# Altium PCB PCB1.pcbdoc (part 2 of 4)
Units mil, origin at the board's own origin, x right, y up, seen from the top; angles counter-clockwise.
Board outline 2559.1 x 3937 mil, 4 copper layers (Top Layer, Inner1, Inner2, Bottom Layer), stack 102.8 mil thick; 377 components, 358 nets, 1639 pads, 361 vias.
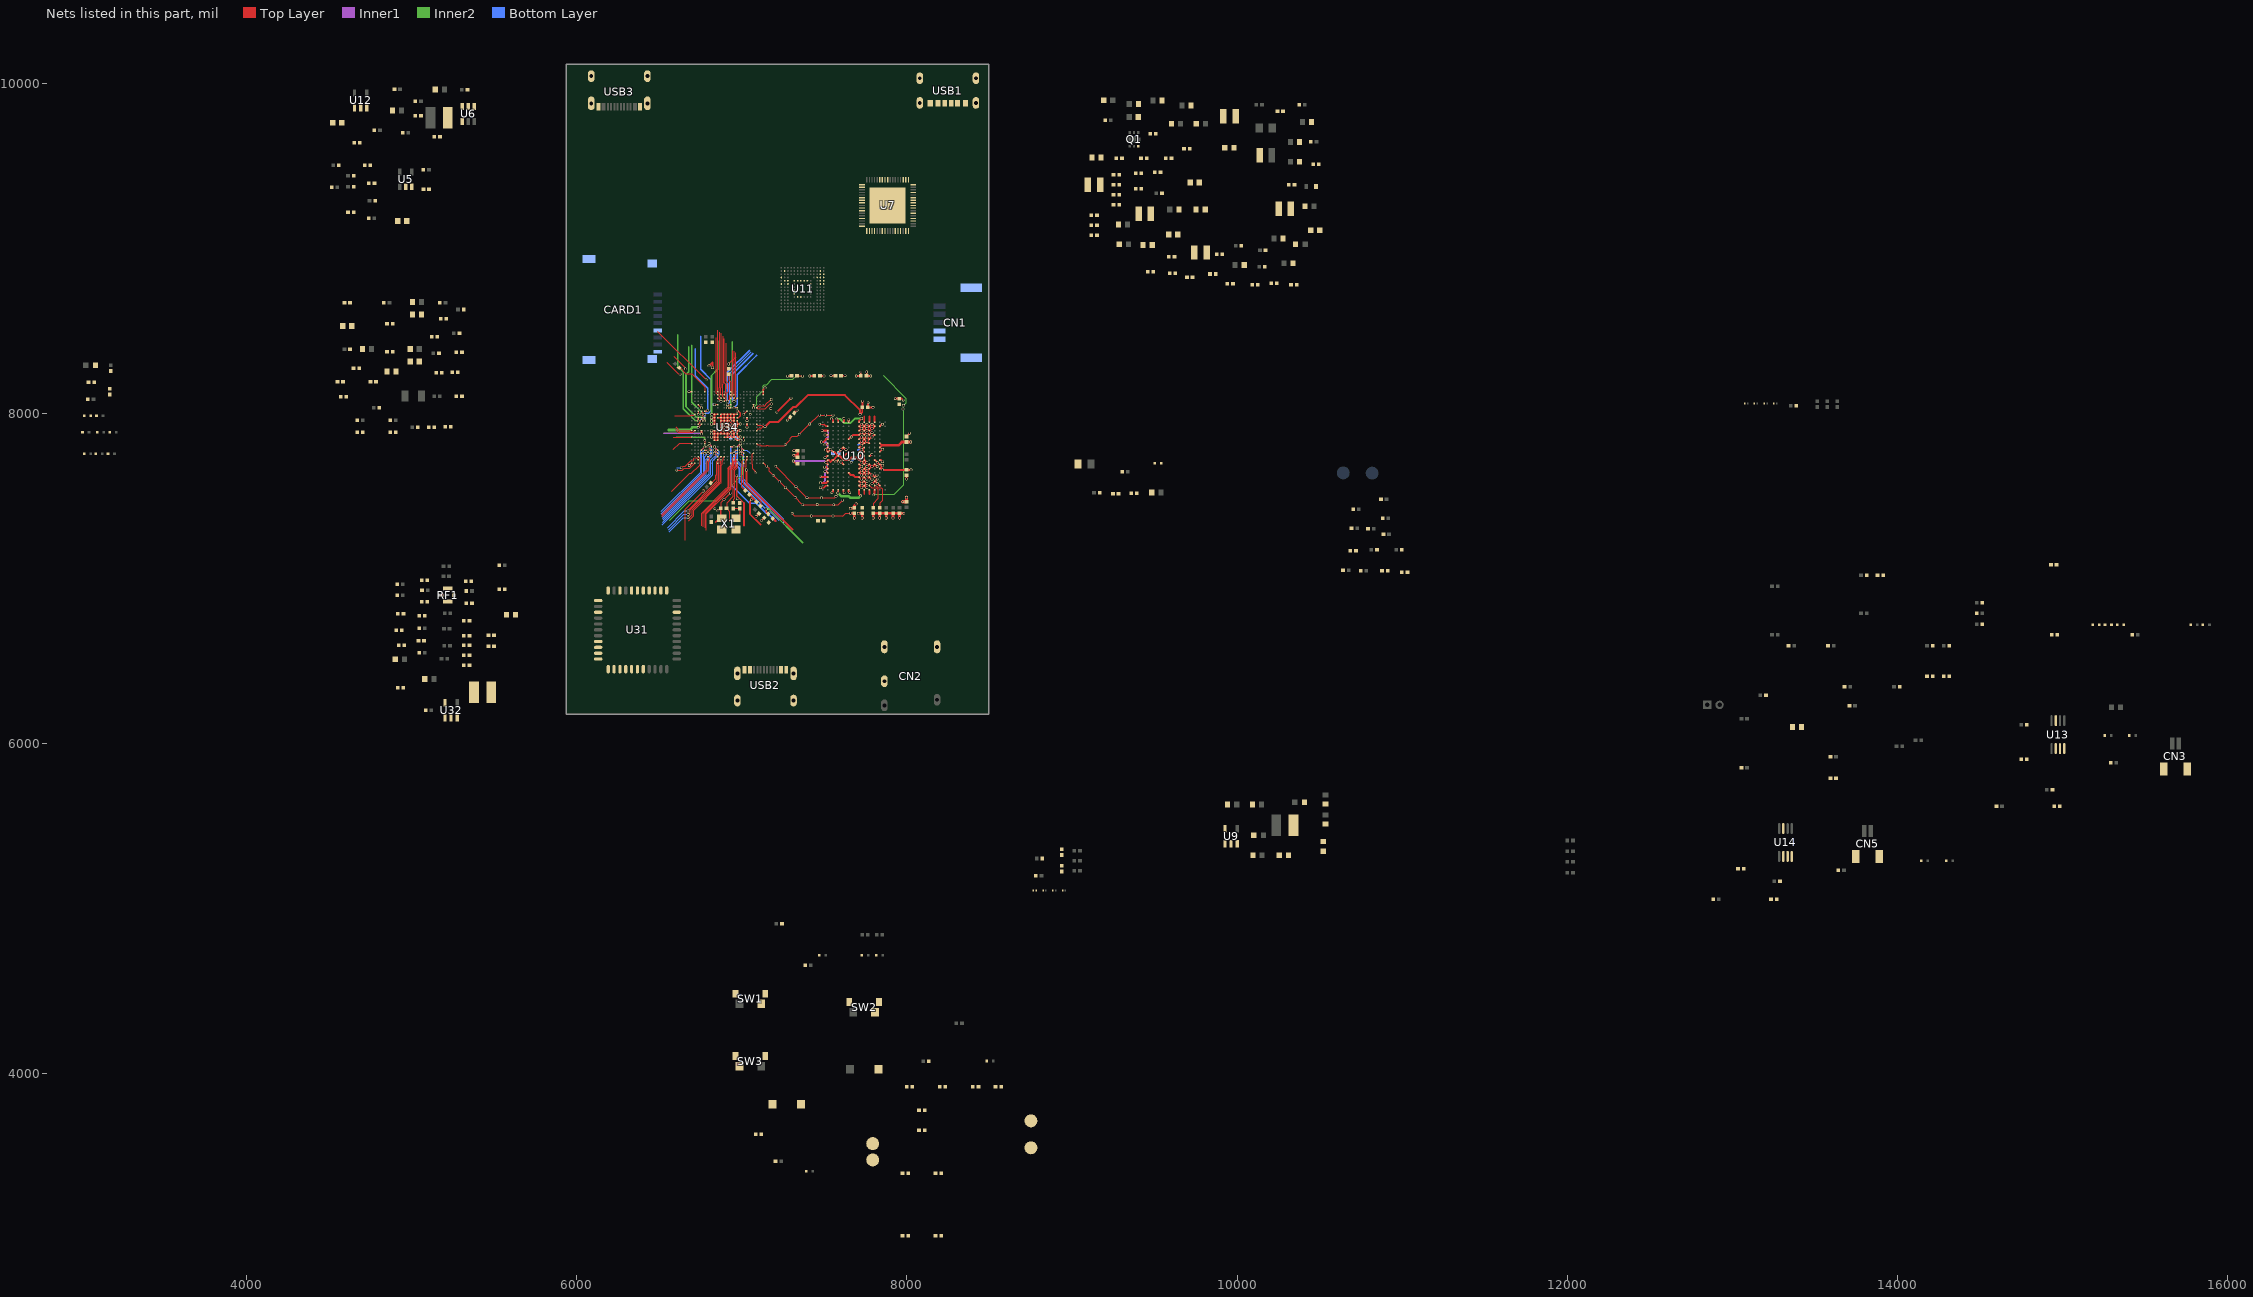
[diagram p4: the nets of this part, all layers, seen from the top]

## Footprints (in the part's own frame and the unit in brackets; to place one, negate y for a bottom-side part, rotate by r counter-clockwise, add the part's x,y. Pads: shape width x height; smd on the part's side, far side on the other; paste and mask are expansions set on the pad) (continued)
TF-SMD_TF-01A [mil]
  rect 23.6x51.2 smd paste+0 mask+2: 1(90.5,207.8) 2(47.2,207.8) 3(3.9,207.8) 4(-39.4,207.8) 5(-82.7,207.8) 6(-126,207.8) 7(-169.3,207.8) 8(-212.6,207.8) 9(-255.9,207.8)
  rect 47.2x55.1 smd paste+0 mask+2: 10(-299.2,174.3) 13(278.7,174.3)
  rect 47.2x78.7 smd paste+0 mask+2: 11(-305.5,-207.7) 12(305.5,-207.7)
  Board Outline Layer lines w0.1: -194.9,-235.3 -191.1,-234.9 -187.4,-233.8 -184,-232 -181,-229.6 -178.5,-226.6 -176.7,-223.2 -175.6,-219.5 -175.2,-215.6 -175.6,-211.8 -176.7,-208.1 -178.5,-204.7 -181,-201.7 -184,-199.3 -187.4,-197.4 -191.1,-196.3 -194.9,-195.9 -198.8,-196.3 -202.4,-197.4 -205.8,-199.3 -208.8,-201.7 -211.3,-204.7 -213.1,-208.1 -214.2,-211.8 -214.6,-215.6 -214.2,-219.5 -213.1,-223.2 -211.3,-226.6 -208.8,-229.6 -205.8,-232 -202.4,-233.8 -198.8,-234.9 -194.9,-235.3 ; 120.1,-235.2 123.9,-234.8 127.6,-233.7 131,-231.9 134,-229.5 136.4,-226.5 138.2,-223.1 139.4,-219.4 139.7,-215.5 139.4,-211.7 138.2,-208 136.4,-204.6 134,-201.6 131,-199.2 127.6,-197.3 123.9,-196.2 120.1,-195.8 116.2,-196.2 112.5,-197.3 109.1,-199.2 106.1,-201.6 103.7,-204.6 101.9,-208 100.7,-211.7 100.4,-215.5 100.7,-219.4 101.9,-223.1 103.7,-226.5 106.1,-229.5 109.1,-231.9 112.5,-233.7 116.2,-234.8 120.1,-235.2
  Board Outline Layer region: -175.2,-215.6 -175.6,-219.5 -176.7,-223.2 -178.5,-226.6 -181,-229.6 -184,-232 -187.4,-233.8 -191.1,-234.9 -194.9,-235.3 -198.8,-234.9 -202.4,-233.8 -205.8,-232 -208.8,-229.6 -211.3,-226.6 -213.1,-223.2 -214.2,-219.5 -214.6,-215.6 -214.2,-211.8 -213.1,-208.1 -211.3,-204.7 -208.8,-201.7 -205.8,-199.3 -202.4,-197.4 -198.8,-196.3 -194.9,-195.9 -191.1,-196.3 -187.4,-197.4 -184,-199.3 -181,-201.7 -178.5,-204.7 -176.7,-208.1 -175.6,-211.8
  Board Outline Layer region: -175.2,-215.6 -175.6,-219.5 -176.7,-223.2 -178.5,-226.6 -181,-229.6 -184,-232 -187.4,-233.8 -191.1,-234.9 -194.9,-235.3 -198.8,-234.9 -202.4,-233.8 -205.8,-232 -208.8,-229.6 -211.3,-226.6 -213.1,-223.2 -214.2,-219.5 -214.6,-215.6 -214.2,-211.8 -213.1,-208.1 -211.3,-204.7 -208.8,-201.7 -205.8,-199.3 -202.4,-197.4 -198.8,-196.3 -194.9,-195.9 -191.1,-196.3 -187.4,-197.4 -184,-199.3 -181,-201.7 -178.5,-204.7 -176.7,-208.1 -175.6,-211.8
  Board Outline Layer region: 139.7,-215.5 139.4,-219.4 138.2,-223.1 136.4,-226.5 134,-229.5 131,-231.9 127.6,-233.7 123.9,-234.8 120.1,-235.2 116.2,-234.8 112.5,-233.7 109.1,-231.9 106.1,-229.5 103.7,-226.5 101.9,-223.1 100.7,-219.4 100.4,-215.5 100.7,-211.7 101.9,-208 103.7,-204.6 106.1,-201.6 109.1,-199.2 112.5,-197.3 116.2,-196.2 120.1,-195.8 123.9,-196.2 127.6,-197.3 131,-199.2 134,-201.6 136.4,-204.6 138.2,-208 139.4,-211.7
  Board Outline Layer region: 139.7,-215.5 139.4,-219.4 138.2,-223.1 136.4,-226.5 134,-229.5 131,-231.9 127.6,-233.7 123.9,-234.8 120.1,-235.2 116.2,-234.8 112.5,-233.7 109.1,-231.9 106.1,-229.5 103.7,-226.5 101.9,-223.1 100.7,-219.4 100.4,-215.5 100.7,-211.7 101.9,-208 103.7,-204.6 106.1,-201.6 109.1,-199.2 112.5,-197.3 116.2,-196.2 120.1,-195.8 123.9,-196.2 127.6,-197.3 131,-199.2 134,-201.6 136.4,-204.6 138.2,-208 139.4,-211.7
  Multi-Layer board cut-out: -175.2,-215.6 -175.6,-219.5 -176.7,-223.2 -178.5,-226.6 -181,-229.6 -184,-232 -187.4,-233.8 -191.1,-234.9 -194.9,-235.3 -198.8,-234.9 -202.4,-233.8 -205.8,-232 -208.8,-229.6 -211.3,-226.6 -213.1,-223.2 -214.2,-219.5 -214.6,-215.6 -214.2,-211.8 -213.1,-208.1 -211.3,-204.7 -208.8,-201.7 -205.8,-199.3 -202.4,-197.4 -198.8,-196.3 -194.9,-195.9 -191.1,-196.3 -187.4,-197.4 -184,-199.3 -181,-201.7 -178.5,-204.7 -176.7,-208.1 -175.6,-211.8
  Multi-Layer board cut-out: 139.7,-215.5 139.4,-219.4 138.2,-223.1 136.4,-226.5 134,-229.5 131,-231.9 127.6,-233.7 123.9,-234.8 120.1,-235.2 116.2,-234.8 112.5,-233.7 109.1,-231.9 106.1,-229.5 103.7,-226.5 101.9,-223.1 100.7,-219.4 100.4,-215.5 100.7,-211.7 101.9,-208 103.7,-204.6 106.1,-201.6 109.1,-199.2 112.5,-197.3 116.2,-196.2 120.1,-195.8 123.9,-196.2 127.6,-197.3 131,-199.2 134,-201.6 136.4,-204.6 138.2,-208 139.4,-211.7
  silkscreen extent -290,-376 290,196
TSOT-23-5_L2.9-W1.6-P0.95-LS2.8-BL#1 [mil]
  rect 20.9x41.1 smd paste+0 mask+2: 1(-37.4,-45.2) 2(0,-45.2) 3(37.4,-45.2) 4(37.4,45.2) 5(-37.4,45.2)
  silkscreen extent -72,-57 61,36
TSOT-23-5_L2.9-W1.6-P0.95-LS2.8-BL#2 [mil]
  rect 20.9x41.1 smd paste+0 mask+2: 1(-37.4,-45.1) 2(0,-45.1) 3(37.4,-45.1) 4(37.4,45.2) 5(-37.4,45.2)
  silkscreen extent -72,-57 61,36
USB-C-SMD_TYPE-C-6P [mil]
  oval 39.4x70.9 hole 23.6 slot 55.1 at 90 deg paste+0 mask+2: 1(-170.1,-75.8) 1(-170.1,73.8) 2(170,-75.8) 2(170,73.8)
  rect 27.6x39.4 smd paste-3937 mask+2: A5(-19.7,75.8) B5(19.7,75.8)
  rect 29.5x39.4 smd paste-3937 mask+2: A9(59.1,75.8) B9(-59,75.8)
  rect 31.5x39.4 smd paste-3937 mask+2: A12(106.3,75.8) B12(-106.3,75.8)
  silkscreen extent -176,-178 176,99
USB-C-SMD_XUNPU_TYPEC-304A-ACP16L#1 [mil]
  oval 39.4x82.7 hole 23.6 slot 66.9 at 90 deg paste+0 mask+2: 25(170.1,71.1) 28(-170,71.1)
  oval 39.4x70.9 hole 23.6 slot 55.1 at 90 deg paste+0 mask+2: 26(170.1,-93.4) 27(-170,-93.4)
  rect 11.8x45.3 smd paste-3937 mask+2: A1(-131.9,93.4) A4(-100.4,93.4) A5(-49.2,93.4) A6(-9.8,93.4) A7(9.9,93.4) A8(49.2,93.4) A9(100.4,93.4) A12(131.9,93.4) B1(120.1,93.4) B4(88.6,93.4) B5(68.9,93.4) B6(29.6,93.4) B7(-29.5,93.4) B8(-68.9,93.4) B9(-88.5,93.4) B12(-120,93.4)
  Board Outline Layer lines w0.1: -126.5,51.5 -126.2,48.4 -125.1,45.5 -123.3,43 -121,40.9 -118.3,39.5 -115.3,38.8 -112.2,38.8 -109.2,39.5 -106.5,40.9 -104.2,43 -102.4,45.5 -101.3,48.4 -100.9,51.5 -101.3,54.5 -102.4,57.4 -104.2,60 -106.5,62 -109.2,63.4 -112.2,64.2 -115.3,64.2 -118.3,63.4 -121,62 -123.3,60 -125.1,57.4 -126.2,54.5 -126.5,51.5 ; 101,51.5 101.4,48.4 102.5,45.5 104.2,43 106.5,40.9 109.3,39.5 112.3,38.8 115.4,38.8 118.4,39.5 121.1,40.9 123.4,43 125.1,45.5 126.2,48.4 126.6,51.5 126.2,54.5 125.1,57.4 123.4,60 121.1,62 118.4,63.4 115.4,64.2 112.3,64.2 109.3,63.4 106.5,62 104.2,60 102.5,57.4 101.4,54.5 101,51.5
  Board Outline Layer region: -100.9,51.5 -101.3,48.4 -102.4,45.5 -104.2,43 -106.5,40.9 -109.2,39.5 -112.2,38.8 -115.3,38.8 -118.3,39.5 -121,40.9 -123.3,43 -125.1,45.5 -126.2,48.4 -126.5,51.5 -126.2,54.5 -125.1,57.4 -123.3,60 -121,62 -118.3,63.4 -115.3,64.2 -112.2,64.2 -109.2,63.4 -106.5,62 -104.2,60 -102.4,57.4 -101.3,54.5
  Board Outline Layer region: -100.9,51.5 -101.3,48.4 -102.4,45.5 -104.2,43 -106.5,40.9 -109.2,39.5 -112.2,38.8 -115.3,38.8 -118.3,39.5 -121,40.9 -123.3,43 -125.1,45.5 -126.2,48.4 -126.5,51.5 -126.2,54.5 -125.1,57.4 -123.3,60 -121,62 -118.3,63.4 -115.3,64.2 -112.2,64.2 -109.2,63.4 -106.5,62 -104.2,60 -102.4,57.4 -101.3,54.5
  Board Outline Layer region: 126.6,51.5 126.2,48.4 125.1,45.5 123.4,43 121.1,40.9 118.4,39.5 115.4,38.8 112.3,38.8 109.3,39.5 106.5,40.9 104.2,43 102.5,45.5 101.4,48.4 101,51.5 101.4,54.5 102.5,57.4 104.2,60 106.5,62 109.3,63.4 112.3,64.2 115.4,64.2 118.4,63.4 121.1,62 123.4,60 125.1,57.4 126.2,54.5
  Board Outline Layer region: 126.6,51.5 126.2,48.4 125.1,45.5 123.4,43 121.1,40.9 118.4,39.5 115.4,38.8 112.3,38.8 109.3,39.5 106.5,40.9 104.2,43 102.5,45.5 101.4,48.4 101,51.5 101.4,54.5 102.5,57.4 104.2,60 106.5,62 109.3,63.4 112.3,64.2 115.4,64.2 118.4,63.4 121.1,62 123.4,60 125.1,57.4 126.2,54.5
  Multi-Layer board cut-out: -100.9,51.5 -101.3,48.4 -102.4,45.5 -104.2,43 -106.5,40.9 -109.2,39.5 -112.2,38.8 -115.3,38.8 -118.3,39.5 -121,40.9 -123.3,43 -125.1,45.5 -126.2,48.4 -126.5,51.5 -126.2,54.5 -125.1,57.4 -123.3,60 -121,62 -118.3,63.4 -115.3,64.2 -112.2,64.2 -109.2,63.4 -106.5,62 -104.2,60 -102.4,57.4 -101.3,54.5
  Multi-Layer board cut-out: 126.6,51.5 126.2,48.4 125.1,45.5 123.4,43 121.1,40.9 118.4,39.5 115.4,38.8 112.3,38.8 109.3,39.5 106.5,40.9 104.2,43 102.5,45.5 101.4,48.4 101,51.5 101.4,54.5 102.5,57.4 104.2,60 106.5,62 109.3,63.4 112.3,64.2 115.4,64.2 118.4,63.4 121.1,62 123.4,60 125.1,57.4 126.2,54.5
  silkscreen extent -176,-196 176,21
USB-C-SMD_XUNPU_TYPEC-304A-ACP16L#2 [mil]
  oval 39.4x82.7 hole 23.6 slot 66.9 at 90 deg paste+0 mask+2: 25(170,71.2) 28(-170.1,71.2)
  oval 39.4x70.9 hole 23.6 slot 55.1 at 90 deg paste+0 mask+2: 26(170,-93.4) 27(-170.1,-93.4)
  rect 11.8x45.3 smd paste-3937 mask+2: A1(-131.9,93.4) A4(-100.4,93.4) A5(-49.2,93.4) A6(-9.9,93.4) A7(9.8,93.4) A8(49.2,93.4) A9(100.4,93.4) A12(131.9,93.4) B1(120,93.4) B4(88.5,93.4) B5(68.9,93.4) B6(29.5,93.4) B7(-29.6,93.4) B8(-68.9,93.4) B9(-88.6,93.4) B12(-120.1,93.4)
  Board Outline Layer lines w0.1: 126.5,51.5 126.2,48.5 125.1,45.6 123.3,43 121,41 118.3,39.6 115.3,38.8 112.2,38.8 109.2,39.6 106.5,41 104.2,43 102.4,45.6 101.3,48.5 100.9,51.5 101.3,54.6 102.4,57.5 104.2,60 106.5,62.1 109.2,63.5 112.2,64.2 115.3,64.2 118.3,63.5 121,62.1 123.3,60 125.1,57.5 126.2,54.6 126.5,51.5 ; -101,51.5 -101.4,48.5 -102.5,45.6 -104.2,43 -106.5,41 -109.3,39.6 -112.3,38.8 -115.4,38.8 -118.4,39.6 -121.1,41 -123.4,43 -125.1,45.6 -126.2,48.5 -126.6,51.5 -126.2,54.6 -125.1,57.5 -123.4,60 -121.1,62.1 -118.4,63.5 -115.4,64.2 -112.3,64.2 -109.3,63.5 -106.5,62.1 -104.2,60 -102.5,57.5 -101.4,54.6 -101,51.5
  Board Outline Layer region: -101,51.5 -101.4,48.5 -102.5,45.6 -104.2,43 -106.5,41 -109.3,39.6 -112.3,38.8 -115.4,38.8 -118.4,39.6 -121.1,41 -123.4,43 -125.1,45.6 -126.2,48.5 -126.6,51.5 -126.2,54.6 -125.1,57.5 -123.4,60 -121.1,62.1 -118.4,63.5 -115.4,64.2 -112.3,64.2 -109.3,63.5 -106.5,62.1 -104.2,60 -102.5,57.5 -101.4,54.6
  Board Outline Layer region: -101,51.5 -101.4,48.5 -102.5,45.6 -104.2,43 -106.5,41 -109.3,39.6 -112.3,38.8 -115.4,38.8 -118.4,39.6 -121.1,41 -123.4,43 -125.1,45.6 -126.2,48.5 -126.6,51.5 -126.2,54.6 -125.1,57.5 -123.4,60 -121.1,62.1 -118.4,63.5 -115.4,64.2 -112.3,64.2 -109.3,63.5 -106.5,62.1 -104.2,60 -102.5,57.5 -101.4,54.6
  Board Outline Layer region: 126.5,51.5 126.2,48.5 125.1,45.6 123.3,43 121,41 118.3,39.6 115.3,38.8 112.2,38.8 109.2,39.6 106.5,41 104.2,43 102.4,45.6 101.3,48.5 100.9,51.5 101.3,54.6 102.4,57.5 104.2,60 106.5,62.1 109.2,63.5 112.2,64.2 115.3,64.2 118.3,63.5 121,62.1 123.3,60 125.1,57.5 126.2,54.6
  Board Outline Layer region: 126.5,51.5 126.2,48.5 125.1,45.6 123.3,43 121,41 118.3,39.6 115.3,38.8 112.2,38.8 109.2,39.6 106.5,41 104.2,43 102.4,45.6 101.3,48.5 100.9,51.5 101.3,54.6 102.4,57.5 104.2,60 106.5,62.1 109.2,63.5 112.2,64.2 115.3,64.2 118.3,63.5 121,62.1 123.3,60 125.1,57.5 126.2,54.6
  Multi-Layer board cut-out: -101,51.5 -101.4,48.5 -102.5,45.6 -104.2,43 -106.5,41 -109.3,39.6 -112.3,38.8 -115.4,38.8 -118.4,39.6 -121.1,41 -123.4,43 -125.1,45.6 -126.2,48.5 -126.6,51.5 -126.2,54.6 -125.1,57.5 -123.4,60 -121.1,62.1 -118.4,63.5 -115.4,64.2 -112.3,64.2 -109.3,63.5 -106.5,62.1 -104.2,60 -102.5,57.5 -101.4,54.6
  Multi-Layer board cut-out: 126.5,51.5 126.2,48.5 125.1,45.6 123.3,43 121,41 118.3,39.6 115.3,38.8 112.2,38.8 109.2,39.6 106.5,41 104.2,43 102.4,45.6 101.3,48.5 100.9,51.5 101.3,54.6 102.4,57.5 104.2,60 106.5,62.1 109.2,63.5 112.2,64.2 115.3,64.2 118.3,63.5 121,62.1 123.3,60 125.1,57.5 126.2,54.6
  silkscreen extent -176,-196 176,21
X3-DFN0603-2_L0.6-W0.3-BI#1 [mil]
  rect 9.1x11.8 smd paste+0 mask+2: 1(-8.6,0) 2(8.7,0)
  silkscreen extent -18,-12 18,12
X3-DFN0603-2_L0.6-W0.3-BI#2 [mil]
  rect 9.1x11.8 smd paste+0 mask+2: 1(-8.7,0) 2(8.7,0)
  silkscreen extent -18,-12 18,12
X3-DFN0603-2_L0.6-W0.3-BI#3 [mil]
  rect 9.1x11.8 smd paste+0 mask+2: 1(-8.7,0) 2(8.6,0)
  silkscreen extent -18,-12 18,12
焊盘 [mil]
  round 78.7 smd paste+0 mask+2: 1(0,0)

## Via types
v1: diameter 16, hole 11.8, Top Layer to Bottom Layer, 361 vias

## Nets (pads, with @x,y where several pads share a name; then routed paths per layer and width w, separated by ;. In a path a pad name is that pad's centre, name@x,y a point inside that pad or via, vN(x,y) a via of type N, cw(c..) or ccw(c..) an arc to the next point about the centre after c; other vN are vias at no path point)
5V-USB1: C146.2 D14.2 R102.1 U12.1 USB2.A4 USB2.A9 USB2.B4 USB2.B9
$1N5746: C97.2 R69.1 U7.34
$1N5747: C98.2 R66.2 U7.28
$1N5783: L4.2 U7.7
$1N5785: C65.2 R44.1 U7.1
$1N5786: C64.2 R46.1 U7.2
$1N5787: C63.2 R45.1 U7.3
$1N5789: C76.2 R54.1 U7.17
$1N5790: C79.2 R55.1 U7.16
$1N5791: C77.2 R56.1 U7.14
$1N5792: C78.2 R57.1 U7.13
$1N5804: C99.2 R67.2 U7.29
$1N5805: C100.2 R68.2 U7.31
$1N5823: R38.2 USB1.A5
$1N5825: R37.2 USB1.B5
$1N5855: R62.2 U7.27
$1N5856: R60.2 U7.26
$1N5860: L6.2 U7.21
$1N5862: L7.2 U7.23
$1N5865: R36.2 U5.3
$1N5867: R33.1 R35.1 U6.1
$1N5874: R41.1 R42.2 U6.6
$1N5877: L3.1 U6.4
$1N5881: C92.2 C93.1 C96.2 L8.2 L9.2 R61.1
$1N5889: Q1.3 U7.52
$1N5894: LED1.1 R58.2
$1N5897: R58.1 U7.53
$1N5906: C70.2 R47.2 U7.68
$1N5913: C103.2 R70.1 U7.35
$1N5915: L9.1 U7.36 U7.37
$1N5916: L8.1 U7.43 U7.44
$1N5924: L5.1 U7.65
$1N26983: C117.2 R188.2 U9.1
$1N27299: L11.1 U9.3
$1N27303: C118.1 R189.1 R190.2 U9.5
$2N2249: R81.1 U10.B3 | length 175
  Top Layer w4: U10.B3@7805.3,7562.2 7814.4,7562.2 7827.6,7548.9 7845.7,7548.9 7850.8,7543.8 7850.8,7470 7835.4,7454.6 R81.1@7835.4,7428.3
$2N2250: R82.1 U10.B4 | length 182.6
  Top Layer w4: U10.B4@7773.2,7563 7787.3,7548.9 7813.6,7548.9 7823.8,7538.7 7823.8,7480.6 7796,7452.8 R82.1@7796,7428.3
$2N5257: R88.1 U34.Y19 | length 474.1
  Top Layer w4: v1(7071.5,8032.8) U34.Y19@7071.5,8052.5 ; R88.1@7335.5,8225.8 7336.2,8225.1 v1(7368.7,8225.1)
  Inner2 w4: v1(7071.5,8032.8) 7091.8,8053 7091.8,8101 7127,8136.2 7127,8163.4 7137.6,8174 7153.1,8174 7183.6,8204.6 7309.2,8204.6 7329.7,8225.1 v1(7368.7,8225.1)
$3N3312: CARD1.9 D12.2 R91.1 R93.1
$3N3345: R103.2 U12.3
$4N5521: R25.2 U34.N23 | length 108
  Top Layer w4: R25.2@6920.9,8233.9 6920.9,8203.5 6933.7,8190.7 U34.N23@6933.7,8131.2
$4N5560: R29.2 U34.E23 | length 232.3
  Top Layer w4: R29.2@6621.1,8275.6 6626.7,8275.6 6662.6,8239.7 6697.3,8239.7 6776.3,8160.8 U34.E23@6776.3,8131.2
$4N5573: R30.2 U34.A9 | length 112.3
  Top Layer w4: 6585.2,7855.6 U34.A9@6697.5,7855.6
$4N5575: R32.2 U34.J2 | length 157.4
  Top Layer w3.5: 6838.6,7621.5 6845.8,7628.7 6845.8,7703 6852.2,7709.3 6852.2,7715.4 U34.J2@6854.8,7718
  Top Layer w4: R32.2@6814.7,7577.2 6838.6,7601.1 6838.6,7621.5
$4N5661: C43.1 U34.U1 | length 304.9
  Top Layer w3.5: 7012.5,7672.7 U34.U1@7012.5,7698.1
  Top Layer w4: 7012.5,7672.7 7012.5,7569.7 7115.4,7466.7 C43.1@7115.4,7435.8
$4N5663: R31.2 U34.U2 | length 199.6
  Top Layer w3.5: 7001.6,7675.8 7001.6,7706.9 U34.U2@7012.5,7717.8
  Top Layer w4: 7001.6,7675.8 7001.6,7552.3 R31.2@7022.5,7531.4
$4N5670: C44.2 U34.P2 | length 485.9
  Top Layer w3.5: 6907.3,7523.4 6929.8,7545.8 6929.8,7660 6949.9,7680.1 6949.9,7709.7 6950.6,7710.3 6950.6,7713.4 6953.4,7716.2 U34.P2@6953.4,7717.8
  Top Layer w4: 6776.5,7305.2 6776.5,7392.5 6907.3,7523.4
$4N5740: C22.2 R27.2 X1.3 | length 108.9
  Top Layer w4: R27.2@6948.9,7423.1 6988.5,7423.1 C22.2@6988.8,7422.8 6988.8,7386.5 X1.3@6965.8,7363.4
$8N2136: C159.2 R146.1 R147.2 U31.2
$8N2137: R146.2 U31.4
$8N2140: R162.1 U31.29
$8N2141: R161.2 U31.24
$8N2146: R148.1 U31.5
$8N2159: R158.1 U31.34
$8N2175: R166.2 U31.28
$8N2176: R163.2 U31.25
$8N2177: R164.2 U31.26
$8N2178: R165.2 U31.27
$8N2187: C163.2 U31.23
$8N2210: R169.1 U32.1
$8N2213: L12.1 U32.3
$8N2214: C167.1 R170.2 R171.1 U32.5
$9N2521: CN2.3 D24.2 R117.2
$9N2522: CN2.4 D33.2 R115.2 R118.2
$9N2523: CN2.5 D23.2 R114.1 R116.1
$9N2527: R129.2 R130.2 U14.4
$9N2534: C155.1 U14.2 U14.3
$9N2537: C152.1 R125.1
$9N2538: R125.2 R126.2 U13.4
$9N2541: C176.1 U13.2 U13.3
$9N2544: C175.2 R121.2
$9N2546: C174.2 R120.2
$9N2604: C157.1 R129.1
$9N2607: C150.2 R122.1 R124.1
$9N2608: C150.1 R127.1 R128.1
ACIN: D5.2 R34.1 U7.57 U7.58 USB1.A9 USB1.B9
AFVCC-CSI: R72.2 R73.2
AGND: C24.1 C25.1 C26.1 R28.1 U34.D11 | length 248.5
  Top Layer w10: v1(6756.6,7875.3) U34.D11@6756.6,7895
  Inner1 w10: 6528.9,7878 6753.8,7878 v1(6756.6,7875.3)
ALDO1: C35.1 C124.1 C125.2 R66.1 R71.1 R89.1 U34.N6 U34.R15 | length 763.4
  Top Layer w10: U34.N6@6933.7,7796.6 v1(6953.4,7796.6) ; U34.R15@6973.1,7973.7 6980.7,7973.7 6990.7,7983.7 6990.7,8001.8 6979.2,8013.4 v1@6973.1,8013.4 ; C35.1@7190.4,7362.3 7190.4,7362 7206.3,7346.1 ; v1(7694,8225.8) R89.1@7721.4,8225.8 v1(7721.4,8249)
  Bottom Layer w10: v1(6953.4,7796.6) 6940.4,7796.6 6934.2,7790.4 6934.2,7568.3 7046.9,7455.5 7088,7455.5 7148.6,7394.9 7157.5,7394.9 7206.3,7346.1
  other v1: 6973,8013.4
ALDO2: C133.1 C134.2 R67.1 R89.2 U10.A3 U10.A4 U10.A5 U10.A6 U10.A10 U10.U3 U10.U4 U10.U5 U10.U6 U10.U10 | length 1614.9
  Top Layer w7.9: v1(7582.5,7517) 7584.9,7519.4 U10.A10@7584.9,7536.6
  Top Layer w10: v1(7756.5,8249.6) 7756.5,8226.9 R89.2@7755.5,8225.8 v1(7781.6,8225.8)
  Top Layer w11.8: v1(7575.9,7966) 7577,7966 7584.9,7958.2 U10.U10@7584.9,7946 ; U10.A6@7710.9,7536.6 7710.9,7510 v1(7721.3,7499.5) ; U10.U6@7710.9,7946 7710.9,7953.1 7725.6,7967.8 v1(7726.2,7967.8) ; 7742.3,7509.3 U10.A5@7742.3,7536.6 ; U10.U5@7742.3,7946 7742.3,7979.1 ; 7773.8,7509.6 U10.A4@7773.8,7536.6 ; U10.U4@7773.8,7946 7773.8,7979.3 ; v1(7799.9,7505.9) 7805.3,7511.4 U10.A3@7805.3,7536.6 ; U10.U3@7805.3,7946 7805.3,7979.5
  Inner2 w4: v1(7799.9,7505.9) 7921.7,7505.9 7979.7,7563.9 v1(7979.7,8048.2) 7981.8,8048.2 7995.2,8061.6 7995.2,8090 7856.4,8228.8
  Inner2 w11.8: v1(7575.9,7966) 7595.5,7966 7619.6,7941.9 7660.3,7941.9 7686.2,7967.8 v1(7726.2,7967.8)
  Inner2 w15: v1(7582.5,7517) 7603.7,7495.9 7649.5,7495.9 7656.5,7488.8 7710.6,7488.8 v1(7721.3,7499.5)
  Bottom Layer w7.9: v1@7580.4,7515.2 7580.7,7515.2 v1(7582.5,7517)
  other v1: 7977,8025.7
ALDO3: R68.1 R182.1
ANT: C160.2 R147.1 RF1.1
AP-CK32K-OUT: R160.1 R161.1 U34.U3 | length 715.9
  Top Layer w4: v1(6992.8,7757.2) U34.U3@7012.5,7737.5
  Inner2 w4: 6564.8,7352.1 6683.8,7471.1 6846.2,7471.1 7005.6,7630.6 7005.6,7744.4 v1(6992.8,7757.2)
AP-NMI: C21.2 R50.1 U7.61 U34.R5 | length 560.1
  Top Layer w4: v1(6954.7,7776.9) U34.R5@6973.1,7776.9 U34.R5@6973.4,7776.6
  Bottom Layer w4: v1(6954.7,7776.9) 6966.6,7765 6966.6,7705.7 6996.1,7676.2 6996.1,7591.5 7173.1,7414.5 7173.1,7404 7228.2,7348.9
AP-RESET: C20.2 R140.1 U7.46 U34.R6 | length 605.3
  Top Layer w4: U34.R6@6973.1,7796.6 v1(6992.8,7816.2)
  Bottom Layer w4: v1(6992.8,7816.2) 6976.9,7800.3 6976.9,7708.8 7003.6,7682.1 7003.6,7594.5 7242.7,7355.4
AP-WAKE-BT: U31.6 U34.R4 | length 543.8
  Top Layer w3.5: 6907.7,7513.2 6936.8,7542.2 6936.8,7656.6 6956.9,7676.7 6956.9,7707.2 6963.2,7713.5 6963.2,7747.3 U34.R4@6973.1,7757.2
  Top Layer w4: 6786.3,7290.8 6786.3,7391.7 6907.7,7513.2
AVCC: C24.2 R71.2 R114.2 R131.2 R132.2 R136.2 U34.D13 | length 213.4
  Top Layer w5: v1(6736.9,7914.7) 6736.9,7914.8 6756.4,7934.4 U34.D13@6756.6,7934.4
  Inner2 w16: 6558.2,7898.5 6686.4,7898.5 6702.5,7914.7 v1(6736.9,7914.7)
AVDD-CSI: R56.2
BOOT-SEL-ADC: R136.1 R139.2 U34.B11 | length 132.3
  Top Layer w3.5: 6596.4,7904.2 6614.8,7885.8 6703.1,7885.8 6712.2,7895 U34.B11@6717.2,7895
BT-PCM-CLK: R164.1 U34.J1 | length 529.5
  Top Layer w3.5: 6845.6,7584.6 6852.8,7591.8 6852.8,7696 U34.J1@6855,7698.1
  Top Layer w4: v1(6674.9,7408.2) 6674.9,7413.9 6845.6,7584.6
  Bottom Layer w4: 6551.9,7306.9 6653.2,7408.2 v1(6674.9,7408.2)
BT-PCM-DIN: R165.1 U34.G6 | length 619.3
  Top Layer w4: v1(6803,7816.7) 6815.6,7804.1 U34.G6@6815.6,7796.6
  Bottom Layer w4: 6522.6,7352.6 6800.9,7630.9 6800.9,7724.8 6819.6,7743.5 6819.6,7786 6815.6,7790 6815.6,7804.1 v1(6803,7816.7)
BT-PCM-DOUT: R163.1 U34.J4 | length 611.6
  Top Layer w4: v1(6835.2,7777.1) 6835.2,7776.9 U34.J4@6855,7757.2
  Bottom Layer w4: 6518.3,7336.3 6810.7,7628.8 6810.7,7711.3 6849,7749.6 6849,7763.3 v1(6835.2,7777.1)
BT-PCM-SYNC: R166.1 U34.G5 | length 589.3
  Top Layer w4: v1(6795.9,7796.8) U34.G5@6815.6,7777.1
  Bottom Layer w4: 6520.5,7362.7 6785.6,7627.8 6785.6,7722.8 6811.9,7749.1 6811.9,7780.8 v1(6795.9,7796.8)
BT-RST-N: R158.2 R159.2 U34.P3 | length 503.2
  Top Layer w3.5: 6904.5,7531.1 6922.8,7549.5 6922.8,7662.9 6942.9,7683 6942.9,7712.6 6943.6,7713.2 6943.6,7727.8 U34.P3@6953.1,7737.3
  Top Layer w4: 6767.2,7311.1 6767.2,7393.9 6904.5,7531.1
BT-UART-CTS: U31.44 U34.K3 | length 591
  Top Layer w3.5: 6856.4,7582.8 6859.8,7586.2 6859.8,7689.1 6864.1,7693.5 6864.1,7713.2 6864.8,7713.9 6864.8,7726.4 U34.K3@6875.2,7736.7
  Top Layer w4: v1(6675.8,7387.1) 6678.5,7387.1 6688.4,7397 6688.4,7414.8 6856.4,7582.8
  Bottom Layer w4: 6556.8,7294.8 6649.2,7387.1 v1(6675.8,7387.1)
BT-UART-RTS: U31.41 U34.L3 | length 481.8
  Top Layer w3.5: 6868.7,7571.7 6873.8,7576.8 6873.8,7683.3 6878.1,7687.7 6878.1,7706.9 6884.5,7713.2 6884.5,7727.7 U34.L3@6894.4,7737.5
  Top Layer w4: 6676,7346.2 6706,7376.3 6706,7409 6868.7,7571.7
BT-UART-RX: R149.1 U31.43 U34.K2 | length 586.5
  Top Layer w3.5: 6863.9,7578 6866.8,7580.9 6866.8,7686.2 6871.1,7690.6 6871.1,7710.3 6874.7,7713.9 U34.K2@6874.7,7717.8
  Top Layer w4: v1(6675.8,7366.9) 6681.5,7366.9 6696.8,7382.2 6696.8,7411 6863.9,7578
  Bottom Layer w4: 6561.2,7281.8 6646.3,7366.9 v1(6675.8,7366.9)
BT-UART-TX: R150.1 U31.42 U34.J5 | length 658.5
  Top Layer w4: v1(6835.2,7796.8) 6855,7777 U34.J5@6855,7776.9
  Bottom Layer w4: 6515.2,7320.4 6820.5,7625.8 6820.5,7708.2 6861.1,7748.7 6861.1,7771 v1(6835.2,7796.8)
BT-WAKE-AP: U31.7 U34.N1 | length 452.6
  Top Layer w3.5: 6901.8,7539 6915.8,7553.1 6915.8,7665.8 6933.7,7683.7 U34.N1@6933.7,7698.1
  Top Layer w4: 6758.5,7318 6758.5,7395.7 6901.8,7539
CPUX-RX: U34.F3 | length 483.5
  Top Layer w3.5: 6790.4,7647.9 6799.5,7656.9 6799.5,7705.9 6805.8,7712.2 6805.8,7727.6 U34.F3@6795.9,7737.5
  Top Layer w4: 6519.3,7376.8 6790.4,7647.9
CPUX-TCK: R144.1 U34.D4 | length 502
  Top Layer w4: U34.D4@6756.6,7757.2 v1@6776.3,7757.2
  Bottom Layer w4: 6516.8,7382.3 6766.2,7631.7 6766.2,7747.2 v1(6776.2,7757.2)
CPUX-TDI: R142.1 U34.D5 | length 532.6
  Top Layer w4: U34.D5@6756.6,7776.9 v1(6776.3,7796.6)
  Bottom Layer w4: 6510.9,7401.9 6748.2,7639.1 6748.2,7768.7 6776.1,7796.6 v1(6776.3,7796.6)
CPUX-TDO: R145.1 U34.G4 | length 519.9
  Top Layer w4: v1(6795.9,7757.2) U34.G4@6815.6,7757.2
  Bottom Layer w4: 6518.3,7372 6776,7629.7 6776,7737.3 v1(6795.9,7757.2)
CPUX-TMS: R143.1 U34.E5 | length 534.4
  Top Layer w4: U34.E5@6776.3,7776.9 v1(6795.9,7776.9)
  Bottom Layer w4: 6514,7392.3 6757,7635.4 6757,7760.7 6773.5,7777.1 6795.7,7777.1 v1(6795.9,7776.9)
CPUX-TX: U34.F2 | length 448.9
  Top Layer w3.5: 6783.3,7652.7 6792.5,7661.9 6792.5,7709.4 6795.9,7712.9 U34.F2@6795.9,7717.8
  Top Layer w4: 6515.6,7385 6783.3,7652.7
CPVDD: C29.2 U34.C15 | length 601.4
  Top Layer w10: v1(6736.9,7954) U34.C15@6736.9,7973.7
  Inner2 w10: 6611.8,8473.9 6611.8,8285.3 6646.4,8250.7 6646.4,8027.5 6719.8,7954 v1(6736.9,7954)
CPVEE: C28.2 U34.D15 U34.E15 | length 1021.2
  Top Layer w4: U34.D15@6756.6,7973.7 v1(6776.3,7954) ; v1(6756.6,7993.4) U34.E15@6776.3,7973.7
  Inner2 w10: 6679.1,8401.6 6679.1,8251.8 6663.1,8235.8 6663.1,8039.8 6728.2,7974.7 6767.6,7974.7 6776.3,7966.1 v1(6776.3,7954) ; 6698.6,8410.3 6697.7,8066 6756.6,8007.1 v1(6756.6,7993.4)
CPVIN: C27.2 C32.1 C33.1 R43.1 R47.1 R183.1 U34.C13 U34.D17 U34.J19 | length 670.3
  Top Layer w4: U34.C13@6736.9,7934.4 v1(6756.6,7954) ; U34.D17@6756.6,8013.1 v1(6776.2,7993.4) ; v1(6835.3,8052.5) U34.J19@6855,8052.5
  Bottom Layer w10: 6751.2,8465.2 6751.2,8266.5 6815.8,8201.8 6815.8,8052.1 ; v1(6756.6,7954) 6756.6,7964.7 6763.8,7972 6769.3,7972 6776.2,7978.9 v1(6776.2,7993.4) 6782.2,7999.4 6798.7,7999.4 6815.8,8016.5 6815.8,8052.1 ; v1(6835.3,8052.5) 6816.2,8052.5 6815.8,8052.1
CTP-INT: U34.B1 | length 128
  Top Layer w3.5: 6686.2,7667.1 U34.B1@6717.2,7698.1
  Top Layer w4: v1(6606.9,7655.4) 6639.9,7655.4 6651.7,7667.1 6686.2,7667.1
CTP-RST: U34.C2 | length 164.6
  Top Layer w3.5: 6687.3,7707.9 6702.7,7707.9 6707.3,7712.5 6707.3,7723.2 6711.8,7727.7 6727.5,7727.7 U34.C2@6737.1,7718
  Top Layer w4: v1(6634.9,7670.4) 6636.7,7670.4 6643.1,7676.9 6656.2,7676.9 6687.3,7708
  Bottom Layer w4: 6606.6,7670.4 v1(6634.9,7670.4)
DC5SET: R52.2 R53.2 U7.62
DCDC1: C51.1 C52.2 C54.1 C86.2 C143.2 C144.1 C145.2 L6.1 R35.2 R48.1 R49.1 R90.2 R91.2 R92.2 R100.2 R108.2 R133.2 R142.2 R143.2 R144.2 R145.2 U7.20 U11.E6 U11.F5 U11.J10 U11.K9 U15.1 U34.E7 U34.R18 | length 598.9
  Top Layer w4: U34.E7@6776.3,7816.3 v1(6776.3,7835.9) ; v1(6953.4,8032.8) U34.R18@6973.1,8032.8
  Inner2 w10: 6605.6,7855.5 6769.4,7855.5 6776.3,7848.6 v1(6776.3,7835.9)
  Bottom Layer w10: v1(6953.4,8032.8) 6973.7,8053 6973.7,8232.9 7090.2,8349.4
DCDC4: C45.1 C46.2 C47.2 C48.2 C49.2 C50.2 C90.2 C91.2 L7.1 R63.1 U34.H13 U34.H14 U34.H15 U34.H16 U34.J16 | length 667.6
  Top Layer w10: v1(6817.2,7934.2) 6835.1,7934.2 U34.H13@6835.3,7934.4 U34.H14@6835.3,7954 ; v1(6817.4,7954) U34.H14@6835.3,7954 ; v1(6817.6,7973.7) U34.H15@6835.3,7973.7 ; v1(6819.3,7992.9) 6834.8,7992.9 U34.H16@6835.3,7993.4 ; U34.J16@6855,7993.4 U34.H16@6835.3,7993.4 ; U34.H14@6835.3,7954 U34.H15@6835.3,7973.7 ; U34.H15@6835.3,7973.7 U34.H16@6835.3,7993.4
  Inner2 w10: v1(6817.2,7934.2) 6817.2,8228.1 6855.9,8266.8 6855.9,8437.1
DCDC5: C69.2 C73.2 C122.1 C123.1 C126.1 C127.2 C128.1 C129.1 C130.2 C131.2 C132.2 C137.1 C138.2 L4.1 R83.2 R84.2 U7.4 U7.8 U10.A8 U10.A9 U10.A11 U10.C12 U10.D4 U10.D5 U10.D6 U10.E8 U10.E12 U10.F2 U10.G2 U10.G5 U10.G12 U10.H3 U10.H5 U10.H6 U10.H8 U10.H9 U10.H11 U10.H12 U10.J5 U10.J6 U10.J9 U10.J10 U10.K5 U10.K6 U10.K8 U10.K11 U10.K12 U10.L2 U10.L5 U10.L12 U10.M2 U10.N8 U10.N12 U10.P4 U10.P5 U10.P6 U10.R12 U10.U8 U10.U9 U10.U11 U34.R9 U34.R10 U34.R11 U34.R12 U34.R13 U34.R14 | length 2972.5
  Top Layer w10: U34.R9@6973.1,7855.6 U34.R10@6973.1,7875.3 U34.R11@6973.1,7895 U34.R12@6973.1,7914.7 U34.R13@6973.1,7934.4 U34.R14@6973.1,7954 ; U34.R9@6973.3,7855.8 v1(6991.2,7855.8) ; U34.R11@6973.3,7895.2 v1(6991.2,7895.2) ; U34.R13@6973.3,7934.5 v1(6991.2,7934.5) ; v1(7312.3,7710.6) 7329.5,7693.3 R84.2@7338.6,7693.3 ; C128.1@7318.6,8001.5 7336.1,8019.1 v1(7336.4,8019.1) ; v1(7412.3,8225.2) 7439.2,8225.2 C127.2@7439.8,8225.8 ; v1(7540.7,8227.3) C126.1@7567.8,8227.3
  Top Layer w11.8: v1(7477.1,7578.8) 7513,7578.8 U10.C12@7521.9,7587.7 ; v1(7482.8,7825.5) 7493.4,7825.5 7511.4,7843.5 U10.N12@7519.2,7843.5 ; v1(7487.7,7894.3) 7488.4,7895.1 U10.R12@7522.3,7895.1 ; v1(7504.7,7646) 7514,7646 U10.E12@7521.1,7638.9 ; v1(7506.9,7778.1) v1@7508.2,7778.1 ; v1@7509.6,7703.3 v1@7509.5,7703.3 ; U10.G12@7521.9,7690.1 7508.6,7703.3 v1@7509.5,7703.3 ; U10.N12@7521.9,7843.6 7519.3,7843.6 U10.N12@7519.2,7843.5 ; U10.L12@7522.1,7792.1 v1@7508.2,7778.1 ; U10.N12@7522.9,7843.5 U10.N12@7519.2,7843.5 ; v1(7544.4,7966) 7545.5,7966 7553.4,7958.2 U10.U11@7553.4,7946 ; v1(7546.3,7518.4) 7553.4,7525.5 U10.A11@7553.4,7536.6 ; U10.A9@7616.4,7536.6 7616.4,7524.4 v1(7622,7518.8) ; U10.U9@7616.4,7946 7619.7,7949.3 7619.7,7967.7 v1(7618.8,7968.7) ; U10.A8@7647.9,7536.6 7647.9,7525.3 v1(7654.5,7518.7) ; U10.E8@7647.9,7638.9 7660.8,7626 7674.3,7626 7687,7613.3 U10.D6@7710.9,7613.3 7723.8,7600.4 v1(7726.6,7600.4) 7739.5,7613.3 U10.D5@7742.3,7613.3 7755.2,7600.4 v1(7758.1,7600.4) 7771,7613.3 U10.D4@7773.8,7613.3 7786.7,7600.4 v1(7789.6,7600.4) ; U10.K8@7647.9,7766.9 7622.3,7741.3 U10.J9@7616.4,7741.3 U10.H9@7616.4,7717.3 ; U10.N8@7647.9,7843.6 7660.8,7856.5 v1(7663.6,7856.5) 7676.3,7869.2 U10.P6@7710.9,7869.2 7723.8,7882.1 v1(7726.6,7882.1) 7729.5,7882.1 U10.P5@7742.3,7869.2 ; U10.U8@7647.9,7946 v1(7647.9,7961.4) ; U10.K6@7710.9,7766.9 7724.5,7780.5 v1(7726.6,7780.5) 7728.8,7780.5 v1@7729.6,7779.7 ; v1(7726.6,7702.8) 7713.7,7715.7 U10.H6@7710.9,7715.7 ; v1(7726.9,7751.5) 7716.7,7741.3 U10.J6@7710.9,7741.3 U10.H6@7710.9,7715.7 ; v1@7729.5,7779.6 v1@7729.6,7779.7 ; U10.J5@7742.3,7741.3 7739.3,7741.3 7742.3,7738.2 U10.H5@7742.3,7715.7 ; U10.L5@7742.3,7792.5 v1@7729.6,7779.7 ; U10.J5@7742.4,7741.3 7729.7,7754 7729.5,7754 7742.4,7766.9 v1@7729.6,7779.7 ; U10.P5@7742.4,7869.2 7755.3,7882.1 v1(7758.1,7882.1) 7761,7882.1 U10.P4@7773.8,7869.2 7786.7,7882.1 v1(7789.6,7882.1) ; v1@7755.2,7703 U10.G5@7742.3,7690.1 7729.7,7702.8 7729.5,7702.8 U10.H5@7742.3,7715.7 ; v1(7758.1,7702.8) 7745.2,7715.7 U10.H5@7742.3,7715.7 ; v1(7766.4,8063.6) 7765.1,8062.2 7765.1,8035.5 v1(7795.1,8035.5) ; U10.H3@7805.3,7715.7 7808.2,7715.7 v1(7821.1,7702.8) 7833.8,7690.1 U10.G2@7836.8,7690.1 7836.8,7689.9 7842.7,7684 v1(7852.8,7684) 7852.8,7680.5 U10.F2@7836.8,7664.5 7846.3,7664.5 v1(7853.8,7656.9) C129.1@7996.7,7656.9 ; U10.L2@7836.8,7792.5 7848.7,7804.3 7848.7,7805.2 ; U10.M2@7836.8,7818.1 7848.7,7806.2 7848.7,7805.4 ; C129.1@7998.3,7658.5 C129.1@7996.7,7656.9 ; v1(8025.3,7656.9) C129.1@7996.7,7656.9 ; v1@7508.2,7778.1 7510.4,7778.1 7522.1,7766.4 7523.5,7766.4 v1(7537.2,7780) 7550.6,7766.7 7559.5,7766.7 U10.J10@7584.9,7741.3 ; v1@7509.5,7703.3 U10.H12@7521.9,7715.7 7528.1,7715.7 7538.1,7705.7 7548,7715.7 U10.H11@7553.4,7715.7 7553.4,7716.2 7578.5,7741.3 U10.J10@7584.9,7741.3 ; U10.J10@7584.9,7741.3 7592.4,7741.3 U10.H9@7616.4,7717.3 ; U10.H9@7616.4,7717.3 U10.H9@7616.4,7715.7 U10.H8@7647.9,7715.7 7664.6,7732.5 7694.1,7732.5 U10.H6@7710.9,7715.7
  Top Layer w16: v1(7659.2,7424.1) 7679.6,7424.1 7682.3,7426.8 C130.2@7682.3,7428.3 7682.3,7440.1 v1(7693.5,7451.3) ; 7848.7,7805.2 7949.3,7805.2 7969.6,7825.5 C132.2@7998.3,7825.5 v1(8023.9,7825.5)
  Top Layer w20: v1(7975.5,7463.8) R83.2@7998.2,7463.8 ; R83.2@7998.3,7463.8 v1(7998.3,7490.3)
  Inner1 w10: v1(7312.3,7710.6) 7501.8,7710.6 v1(7509.6,7702.7) 7519.2,7693.2 7519.2,7660.5 v1(7504.7,7646) 7504.7,7590.7 7492.8,7578.8 v1(7477.1,7578.8) ; v1(7482.8,7825.5) 7509.3,7825.5 7510,7826.3 ; v1(7487.7,7894.3) 7514.4,7894.3 7524.8,7883.9 7524.8,7858.2 7510,7843.4 7510,7826.3 ; v1(7506.9,7778.1) 7521,7792.2 7521,7815.3 7510,7826.3
  Bottom Layer w10: C138.2@6968.3,7930.8 6972,7934.5 v1(6991.2,7934.5) ; C137.1@6968.5,7852.4 6971.9,7855.8 v1(6991.2,7855.8) ; v1(7537.2,7780) 7550.8,7766.4 C122.1@7550.8,7755.8 ; v1@7540.7,8226.8 v1(7540.7,8227.3) ; 7702.8,7776 7707.3,7780.5 v1(7726.6,7780.5) ; 7718.8,7727.9 7726.9,7736 v1(7726.9,7751.5)
DCDC-WIFI: C165.2 C166.1 C167.2 L12.2 R168.1 R171.2
DCXO-XIN: C18.2 U34.R2 X1.1 | length 409.7
  Top Layer w3.5: 6946.4,7654.1 6963.9,7671.6 6963.9,7704.3 6970.2,7710.6 6970.2,7715 U34.R2@6973.1,7717.8
  Top Layer w4: 6924.2,7341.6 6924.2,7407.6 C18.2@6908.3,7423.5 6908.3,7454.8 6946.4,7492.9 6946.4,7654.1
DCXO-XOUT: R27.1 U34.R1 | length 251.3
  Top Layer w4: R27.1@6948.9,7457.2 6948.4,7457.7 6948.4,7476.2 6955.4,7483.2 6955.4,7652.3 6973.1,7670 U34.R1@6973.1,7698.1
DDR-PARA-SEL-ADC: R132.1 R137.2 U34.A11 | length 108.2
  Top Layer w4: 6599.2,7918.8 6623,7895 U34.A11@6697.5,7895
DDR-PARA-SEL-GPIO: R133.1 R138.2 U34.C3 | length 293.9
  Top Layer w3.5: U34.C3@6736.9,7737.5 6746.7,7727.7 6746.7,7714.8 6746.1,7714.2 6746.1,7687.1 6738.6,7679.7
  Top Layer w4: 6574.1,7524.7 6683.4,7634 6692.9,7634 6738.6,7679.7
DLDO1: R54.2 R64.2 R167.1
DLDO2: C55.1 R55.2 R72.1 U34.E17 | length 422.8
  Top Layer w10: U34.E17@6776.3,8013.1 6776.4,8013 6789,8013 v1(6793.1,8017)
  Bottom Layer w10: 6718.4,8390 6718.4,8227.4 6793.6,8152.2 6793.6,8017.6 v1(6793.1,8017)
DLDO4: R57.2 R73.1
DVDD-CSI: R44.2
EINT-HAL: U34.U4 | length 586.4
  Top Layer w4: v1(6992.8,7776.9) U34.U4@7012.5,7757.2
  Bottom Layer w4: v1(6992.8,7776.9) 7011.1,7758.6 7011.1,7599.8 7253.3,7357.6 7253.3,7326.3
ELDO3: C56.1 R46.2 R65.2 U34.N18 | length 438.2
  Top Layer w4: v1@6914,8032.8 U34.N18@6933.7,8032.8
  Inner2 w10: v1(6914.1,8032.8) 6926.1,8032.8 6934,8040.7 6934,8094.8 6943.2,8103.9 6943.2,8432.2
EMMC-CLK: R25.1 U11.M6 | length 66.1
  Top Layer w4: R25.1@6921.1,8276.2 6920.7,8275.8 R25.1@6922.3,8274.1 ; v1(6921.4,8298.6) 6966.1,8343.3
EMMC-CMD: R94.2 U11.M5 U34.L22 | length 376.9
  Top Layer w3.5: U34.L22@6894.4,8111.5 6894.4,8116.3 6905,8127 6905,8149 6904.4,8149.6
  Top Layer w4: 6892.7,8452.5 6892.7,8186.9 6904.4,8175.2 ; 6904.4,8149.6 6904.4,8175.2 ; 6905,8149 6905,8174.6 6904.4,8175.2
EMMC-D0: U11.A3 U34.K22 | length 371.7
  Top Layer w3.5: U34.K22@6874.7,8111.5 6874.7,8153.9
  Top Layer w4: 6874.7,8153.9 6874.7,8483.2
EMMC-D1: U11.A4 U34.L21 | length 378.6
  Top Layer w3.5: 6884.5,8175.6 6884.5,8101.7 U34.L21@6894.4,8091.8
  Top Layer w4: 6884.5,8175.6 6884.5,8466.3
EMMC-D2: U11.A5 U34.J23 | length 372.8
  Top Layer w3.5: U34.J23@6855,8131.2 6855,8154
  Top Layer w4: 6855,8154 6855,8504
EMMC-D3: U11.B2 U34.P21 | length 279
  Top Layer w3.5: U34.P21@6953.4,8091.8 6963.2,8101.6 6963.2,8143.7
  Top Layer w4: 6963.2,8143.7 6963.2,8366.7
EMMC-D4: U11.B3 U34.N21 | length 291.1
  Top Layer w3.5: U34.N21@6933.7,8091.8 6943.6,8101.7 6943.6,8146.7
  Top Layer w4: 6943.6,8146.7 6943.6,8378.8
EMMC-D5: U11.B4 U34.J22 | length 349.4
  Top Layer w3.5: 6845.1,8153.7 6845.1,8121.4 U34.J22@6855,8111.5
  Top Layer w4: 6845.1,8153.7 6845.1,8456.8
EMMC-D6: U11.B5 U34.K21 | length 404.1
  Top Layer w3.5: 6864.8,8153.5 6864.8,8101.7 U34.K21@6874.7,8091.8
  Top Layer w4: 6864.8,8153.5 6864.8,8491.8
EMMC-D7: U11.B6 U34.L20 | length 367.3
  Top Layer w3.5: U34.L20@6894.4,8072.2 6904.2,8082 6904.2,8115.8 6917.7,8129.3 6917.7,8148.6
  Top Layer w4: 6902.9,8423.7 6902.9,8196.4 6917.7,8181.6 6917.7,8148.6
EMMC-DS: R96.2 U11.H5 U34.N19 | length 399.5
  Top Layer w4: v1(6914,8052.5) U34.N19@6933.7,8052.5
  Bottom Layer w4: v1(6914,8052.5) 6928.1,8066.5 6928.1,8242.4 7058.2,8372.6
EMMC-RST: R95.2 U11.K5 U34.P22 | length 263.7
  Top Layer w3.5: U34.P22@6953.2,8111.7 6953.2,8148.3
  Top Layer w4: 6953.2,8148.3 6953.2,8375.4
FEL: C181.2 SW5.1 U16.1 U34.A7 | length 131
  Top Layer w4: 6582.6,7777.6 6621.2,7816.3 U34.A7@6697.5,7816.3
FLDO1: C42.1 R45.2 R59.1 U34.N4 | length 779.6
  Top Layer w4: U34.N4@6933.6,7757.1 U34.N4@6933.7,7757.2 v1(6953.1,7757.2)
  Top Layer w10: v1(7148.2,7420.2) 7148.2,7404.1 C42.1@7160.9,7391.4
  Inner2 w10: v1(7148.2,7420.2) 7165.6,7420.2 7370.5,7215.3
  Bottom Layer w10: v1(6953.1,7757.2) 6953.1,7699.7 6985.6,7667.2 6985.6,7581 7146.4,7420.2 v1(7148.2,7420.2)
GND: C18.1 C19.2 C20.1 C21.1 C22.1 C23.2 C27.1 C28.1 C29.1 C30.2 C31.2 C32.2 C33.2 C34.2 C35.2 C36.2 C37.1 C38.1 C39.1 C40.1 C41.1 C42.2 C43.2 C44.1 C45.2 C46.1 C47.1 C48.1 C49.1 C50.1 C51.2 C52.1 C53.2 C54.2 C55.2 C56.2 C57.2 C58.2 C59.1 C60.2 C61.1 C62.1 C63.1 C64.1 C65.1 C67.1 C68.1 C69.1 C70.1 C71.2 C72.2 C73.1 C74.2 C76.1 C77.1 C78.1 C79.1 C80.2 C81.2 C82.2 C83.2 C84.2 C85.1 C86.1 C87.1 C88.1 C89.1 C90.1 C91.1 C92.1 C93.2 C94.2 C95.2 C96.1 C97.1 C98.1 C99.1 C100.1 C101.2 C102.2 C103.1 C115.1 C116.1 C117.1 C119.1 C120.1 C121.1 C122.2 C123.2 C124.2 C125.1 C126.2 C127.1 C128.2 C129.2 C130.1 C131.1 C132.1 C133.2 C134.1 C135.1 C136.1 C137.2 C138.1 C139.1 C140.2 C141.1 C142.2 C143.1 C144.2 C145.1 C146.1 C147.1 C148.1 C149.2 C151.1 C154.1 C155.2 C156.1 C158.1 C159.1 C160.1 C161.1 C162.1 C163.1 C164.1 C165.1 C166.2 C170.1 C171.1 C173.1 C176.2 C178.2 C180.2 C181.1 C182.2 CARD1.6 CARD1.10 CARD1.11 CARD1.12 CARD1.13 CN1.4 CN1.5 CN1.6 CN1.7 CN3.3 CN3.4 CN5.3 CN5.4 D5.1 D7.1 D8.1 D9.1 D10.1 D11.1 D12.1 D13.1 D14.1 D15.1 D16.1 D17.1 D18.1 D19.1 D20.1 D21.1 D22.1 D23.1 D24.1 D25.1 D26.1 D27.1 D28.1 D31.1 D32.1 D33.1 D34.1 D35.1 D36.1 D37.1 D38.1 R28.2 R31.1 R36.1 R37.1 R38.1 R39.1 R40.1 R42.1 R53.1 R81.2 R82.2 R85.1 R86.1 R88.2 R96.1 R101.1 R103.1 R104.1 R118.1 R119.1 R120.1 R121.1 R123.2 R128.2 R137.1 R138.1 R139.1 R148.2 R157.1 R159.1 R162.2 R170.1 R190.1 RF1.2 RF1.3 RF1.4 SW1.1 SW1.2 SW1.4 SW2.1 SW2.2 SW2.4 SW3.1 SW3.2 SW3.3 SW4.2 SW5.2 U5.2 U6.5 U7.12 U7.25 U7.45 U7.59 U7.69 U9.2 U10.B2 U10.B5 U10.B6 U10.B12 U10.C3 U10.C5 U10.C6 U10.D3 U10.D12 U10.E4 U10.E5 U10.E6 U10.F4 U10.F5 U10.F6 U10.F12 U10.G3 U10.G4 U10.G6 U10.G9 U10.H2 U10.H10 U10.J4 U10.J12 U10.K2 U10.K10 U10.L6 U10.L9 U10.M4 U10.M5 U10.M6 U10.M12 U10.N4 U10.N5 U10.N6 U10.P3 U10.P12 U10.R4 U10.R5 U10.R6 U10.T2 U10.T3 U10.T4 U10.T5 U10.T6 U10.T12 U11.A6 U11.C4 U11.E7 U11.G5 U11.H10 U11.J5 U11.K8 U11.N2 U11.N5 U11.P4 U11.P6 U12.2 U13.7 U14.7 U27.1 U30.1 U31.1 U31.3 U31.20 U31.31 U31.33 U31.36 U32.2 U34.A1 U34.A23 U34.AA7 U34.AA11 U34.AA13 U34.AA18 U34.AC1 U34.AC22 U34.AC23 U34.C17 U34.C19 U34.H8 U34.H9 U34.H10 U34.H11 U34.J3 U34.J8 U34.J9 U34.J10 U34.J15 U34.J21 U34.K10 U34.K11 U34.K12 U34.K13 U34.K14 U34.K15 U34.K16 U34.L9 U34.L10 U34.L14 U34.L15 U34.L16 U34.M9 U34.M10 U34.M11 U34.M12 U34.M13 U34.M14 U34.M15 U34.M16 U34.N9 U34.N15 U34.N16 U34.N22 U34.P9 U34.P10 U34.P11 U34.P12 U34.P13 U34.P14 U34.P15 U34.P16 U34.R8 U34.R16 U34.R21 U34.U5 U34.U9 U34.V2 U34.V3 U34.V13 U34.V15 U34.V17 U34.Y4 USB1.1 USB1.2 USB1.A12 USB1.B12 USB2.25 USB2.26 USB2.27 USB2.28 USB2.A1 USB2.A12 USB2.B1 USB2.B12 USB3.25 USB3.26 USB3.27 USB3.28 USB3.A1 USB3.A12 USB3.B1 USB3.B12 X1.2 X1.4 | length 11269.3
  Top Layer w3.5: v1(6914,8072.2) 6923.9,8082 6923.9,8101.7 U34.N22@6933.7,8111.5 ; U34.Y4@7071.5,7757.2 7061.7,7747.4 7061.7,7693.4 7064.3,7690.8 7064.3,7667 7081.9,7649.3 v1(7081.9,7639.2) ; U34.AA11@7091.8,7895.4 7101.2,7904.8 7115.9,7904.8 7129.9,7918.7 ; U34.AA13@7092.6,7933.4 7101.5,7924.5 7114.1,7924.5 ; U34.AA7@7092.7,7815.5 7101.7,7806.4 7115.1,7806.4 7120.7,7800.8 7123.9,7800.8 7124.7,7800.1 7147.8,7800.1 7149.6,7801.9 7160.5,7801.9 ; v1(7179.8,8083.2) 7175.2,8083.2 7147,8055 7147,8052.3 7137.4,8042.7 7101.1,8042.7 U34.AA18@7091.2,8032.8 7101.1,8022.9 7139.2,8022.9 7172.4,8056.1 v1(7180.6,8056.1)
  Top Layer w4: 6653.8,7232 6653.8,7415.7 v1(6766.9,7528.7) 6774.5,7536.3 6774.5,7538.6 ; v1(6736.9,7993.4) U34.C17@6736.9,8013.1 ; U34.C19@6736.9,8052.5 v1(6756.6,8032.8) ; v1(6835.3,7757.2) U34.J3@6855,7737.5 ; C18.1@6874.2,7423.5 6874.2,7458.9 v1(6892.8,7477.5) v1(6931.8,7516.4) ; v1(6953.4,8072.2) U34.R21@6973.1,8091.8 ; v1(6992.8,7796.6) U34.U5@7012.5,7776.9 ; v1(7012.2,7837) 7012.2,7855.3 U34.U9@7012.5,7855.6 ; v1(7012.2,7992.9) 7032.2,8012.9 U34.V17@7032.2,8013.1 ; U34.V2@7032.2,7717.8 U34.V3@7032.2,7737.5 ; 7114.1,7924.5 7123.1,7924.5 7128.8,7918.7 7129.9,7918.7 v1(7141.3,7918.7) ; U34.AC1@7130.6,7698.1 7133.3,7698.1 7151.7,7679.8 7165.5,7666 7165.5,7649.2 v1(7190.3,7624.4) v1(7229.9,7584.8) 7230.6,7584.8 v1(7265.6,7549.8) 7323.8,7491.6 v1(7323.8,7490.6) 7367.9,7446.4 v1(7369.2,7446.4) 7369.8,7447 v1(7457.7,7447) 7459,7445.7 v1(7557.2,7445.7) 7583.9,7445.7 v1(7611.9,7473.8) ; 7160.5,7801.9 7256.4,7801.9 v1(7263.6,7809.1) 7293.6,7839 7293.6,7847.7 7305.7,7859.8 7337.1,7859.8 v1(7349.3,7872) v1(7412.2,7935) 7465.3,7988 v1(7508.8,7988) 7553,7988 v1(7553.2,7988.3) ; v1(7206.2,7678) v1(7329,7555.2) v1(7395.4,7488.8) 7396.6,7487.6 v1(7483.6,7487.6) 7562.4,7487.6 v1(7571.5,7496.7) ; v1(7477.1,7549.3) 7497.5,7549.3
  Top Layer w5: v1(7472.6,7933.3) 7498,7933.3
  Top Layer w6: 6492.8,8494.4 v1(6784.7,8202.6) ; 6548,8306.9 6618.5,8236.5 v1(6627.2,8236.5) ; 6591.2,8343.2 6658.4,8276 v1(6658.4,8268.8) ; v1(7028.4,7655.9) 7028.4,7671 7024.4,7675 7024.4,7710 U34.V2@7032.2,7717.8 ; v1(7305.4,7394.3) 7322.2,7377.5 v1(7421.6,7377.5) v1(7552.9,7377.5) 7612.7,7377.5 7629.7,7394.5 v1(7658.4,7394.5)
  Top Layer w8: v1(6681.1,8130.8) 6681.5,8131.2 U34.A23@6697.5,8131.2 ; v1@6682.7,7683.3 U34.A1@6697.5,7698.1 ; 7497.5,7549.3 7510.4,7562.2 U10.B12@7521.9,7562.2 ; 7498,7933.3 7510.8,7920.4 U10.T12@7521.9,7920.4
  Top Layer w9: U34.AC22@7130.6,8111.5 U34.AC23@7130.6,8131.2 7130.6,8143 v1(7141,8153.4)
  Top Layer w10: v1(6802.1,8287.4) 6823.2,8308.5 v1(6823.2,8276.1) ; v1(6817.2,7855.4) U34.H9@6835.1,7855.4 ; v1(6817.2,7875.1) 6835.1,7875.1 U34.H10@6835.3,7875.3 ; v1(6817.2,7894.8) U34.H11@6835.1,7894.8 ; 6842.5,7340.9 6865,7363.4 X1.4@6879.1,7363.4 6874.2,7368.3 C18.1@6874.2,7423.5 6870.6,7423.5 v1(6855.6,7408.5) ; U34.J15@6855,7973.7 U34.K15@6874.7,7973.7 ; U34.J21@6855,8091.8 v1(6874.7,8072.2) ; U34.L9@6894.4,7855.6 U34.M9@6914,7855.6 ; v1(6969.1,7621.8) 6969.1,7501 7014.1,7456 7014.1,7319.7 ; U34.R16@6973.1,7993.4 U34.P16@6953.4,7993.4 ; v1(6992.8,7835.9) U34.R8@6973.1,7835.9 U34.P9@6953.4,7855.6 ; v1(7031.9,7915.7) 7032.2,7916 U34.V13@7032.2,7934.4 ; v1(7032.2,7955.3) U34.V15@7032.2,7973.7 ; R31.1@7046.6,7507.3 7068.2,7485.7 ; v1(7088.1,7375.4) C57.2@7104.6,7391.9 ; C43.2@7091.3,7459.9 7091.3,7462.6 7068.2,7485.7 ; 7115.1,7323.8 7050.2,7388.7 7050.2,7467.6 v1(7058.8,7476.2) 7068.2,7485.7 ; v1@7120.3,7350.4 C42.2@7136.8,7366.8 ; v1(7275.9,7958.3) 7275.9,7958.8 C128.2@7294.5,7977.4 ; v1(7277.2,8224.3) 7299.9,8224.3 R88.2@7301.4,8225.8 ; C127.1@7473.9,8225.8 v1(7498.6,8225.8) ; v1(7504.3,7731) 7514.6,7741.3 U10.J12@7521.9,7741.3 ; C126.2@7601.9,8227.3 v1(7626.7,8227.3) ; C132.1@7998.3,7859.6 8017.1,7878.4 v1(8017.1,7879.5) ; U34.H9@6835.1,7855.4 U34.H9@6835.3,7855.4 ; U34.H9@6835.1,7855.4 U34.H9@6835.3,7855.6 ; U34.H11@6835.1,7894.8 U34.H11@6835.3,7894.8 ; U34.H11@6835.1,7894.8 U34.H11@6835.3,7895 U34.H11@6835.3,7894.8 ; U34.H9@6835.3,7855.4 U34.H8@6835.3,7835.9 6835.1,7835.8 6854.8,7835.8 U34.J8@6855,7835.9 U34.J9@6855,7855.6 ; U34.H9@6835.3,7855.4 6854.8,7855.4 U34.J9@6855,7855.6 ; U34.H9@6835.3,7855.4 U34.H9@6835.3,7855.6 ; U34.H9@6835.3,7855.6 U34.H10@6835.3,7875.3 ; U34.H10@6835.3,7875.3 U34.J10@6855,7875.3 ; U34.H10@6835.3,7875.3 U34.H11@6835.3,7894.8 ; U34.H11@6835.3,7894.8 v1@6854.9,7894.8 ; v1@6854.9,7894.8 6855,7894.7 U34.J10@6855,7875.3 ; v1@6854.9,7894.8 6874.5,7894.8 U34.K11@6874.7,7895 ; U34.J9@6855,7855.6 U34.J10@6855,7875.3 ; U34.J10@6855,7875.3 U34.K10@6874.7,7875.3 ; U34.K10@6874.7,7875.3 U34.L10@6894.4,7875.3 ; U34.K10@6874.7,7875.3 U34.K11@6874.7,7895 ; U34.K11@6874.7,7895 v1(6894.4,7895) ; U34.K11@6874.7,7895 U34.K12@6874.7,7914.7 ; U34.K12@6874.7,7914.7 v1(6894.4,7914.7) ; U34.K12@6874.7,7914.7 U34.K13@6874.7,7934.4 ; U34.K13@6874.7,7934.4 v1(6894.4,7934.4) ; U34.K13@6874.7,7934.4 U34.K14@6874.7,7954 ; U34.K14@6874.7,7954 U34.L14@6894.4,7954 ; U34.K14@6874.7,7954 U34.K15@6874.7,7973.7 ; U34.K15@6874.7,7973.7 U34.L15@6894.4,7973.7 ; U34.K15@6874.7,7973.7 U34.K16@6874.7,7993.4 U34.L16@6894.4,7993.4 ; U34.L10@6894.4,7875.3 U34.M10@6914,7875.3 ; U34.L10@6894.4,7875.3 v1(6894.4,7895) ; v1(6894.4,7895) U34.M11@6914,7895 ; v1(6894.4,7895) v1(6894.4,7914.7) ; v1(6894.4,7914.7) U34.M12@6914,7914.7 ; v1(6894.4,7914.7) v1(6894.4,7934.4) ; v1(6894.4,7934.4) U34.M13@6914,7934.4 ; v1(6894.4,7934.4) U34.L14@6894.4,7954 ; U34.L14@6894.4,7954 U34.M14@6914,7954 ; U34.L14@6894.4,7954 U34.L15@6894.4,7973.7 ; U34.L15@6894.4,7973.7 U34.M15@6914,7973.7 ; U34.L15@6894.4,7973.7 U34.L16@6894.4,7993.4 ; U34.L16@6894.4,7993.4 U34.M16@6914,7993.4 ; U34.M9@6914,7855.6 U34.N9@6933.7,7855.6 ; U34.M9@6914,7855.6 U34.M10@6914,7875.3 ; U34.M10@6914,7875.3 v1(6933.7,7875.3) ; U34.M10@6914,7875.3 U34.M11@6914,7895 ; U34.M11@6914,7895 v1(6933.7,7895) ; U34.M11@6914,7895 U34.M12@6914,7914.7 ; U34.M12@6914,7914.7 v1(6933.7,7914.7) ; U34.M12@6914,7914.7 U34.M13@6914,7934.4 ; U34.M13@6914,7934.4 v1(6933.7,7934.4) ; U34.M13@6914,7934.4 U34.M14@6914,7954 ; U34.M14@6914,7954 v1(6933.7,7954) ; U34.M14@6914,7954 U34.M15@6914,7973.7 ; U34.M15@6914,7973.7 U34.N15@6933.7,7973.7 ; U34.M15@6914,7973.7 U34.M16@6914,7993.4 ; U34.M16@6914,7993.4 U34.N16@6933.7,7993.4 ; U34.N9@6933.7,7855.6 U34.P9@6953.4,7855.6 ; U34.N9@6933.7,7855.6 v1(6933.7,7875.3) ; v1(6933.7,7875.3) U34.P10@6953.4,7875.3 ; v1(6933.7,7875.3) v1(6933.7,7895) ; v1(6933.7,7895) U34.P11@6953.4,7895 ; v1(6933.7,7895) v1(6933.7,7914.7) ; v1(6933.7,7914.7) U34.P12@6953.4,7914.7 ; v1(6933.7,7914.7) v1(6933.7,7934.4) ; v1(6933.7,7934.4) U34.P13@6953.4,7934.4 ; v1(6933.7,7934.4) v1(6933.7,7954) ; v1(6933.7,7954) U34.P14@6953.4,7954 ; v1(6933.7,7954) U34.N15@6933.7,7973.7 ; U34.N15@6933.7,7973.7 U34.P15@6953.4,7973.7 ; U34.N15@6933.7,7973.7 U34.N16@6933.7,7993.4 ; U34.N16@6933.7,7993.4 U34.P16@6953.4,7993.4 ; U34.P9@6953.4,7855.6 U34.P10@6953.4,7875.3 ; U34.P10@6953.4,7875.3 U34.P11@6953.4,7895 ; U34.P11@6953.4,7895 U34.P12@6953.4,7914.7 ; U34.P12@6953.4,7914.7 U34.P13@6953.4,7934.4 ; U34.P13@6953.4,7934.4 U34.P14@6953.4,7954 ; U34.P14@6953.4,7954 U34.P15@6953.4,7973.7 ; U34.P15@6953.4,7973.7 U34.P16@6953.4,7993.4
  Top Layer w11.8: v1(7028.4,7655.9) 7028.4,7576.1 7307.3,7297.2 ; v1(7141.3,7918.7) 7169.5,7946.9 7220.4,7946.9 7311.2,8037.8 7327.9,8037.8 7400.5,8110.3 7625.7,8110.3 7716.9,8019.1 v1(7716.9,7993) 7730.2,8006.3 C131.1@7730.2,8029.1 ; v1@7213.3,8006.6 v1(7298.5,8091.8) ; v1(7475.4,7619.3) 7481.3,7613.3 U10.D12@7521.9,7613.3 ; v1(7501.8,7673.8) 7512.6,7673.8 U10.F12@7521.9,7664.5 ; v1(7504.3,7808.7) 7512.2,7808.7 U10.M12@7521.1,7817.7 ; v1(7504.7,7867.9) 7514.3,7867.9 7515.7,7869.2 U10.P12@7521.9,7869.2 ; v1(7571,7705.2) 7574.4,7705.2 U10.H10@7584.9,7715.7 ; U10.K10@7584.9,7766.9 7590.8,7766.9 v1@7603.5,7779.6 ; v1(7600.6,7704.8) 7601.7,7704.8 U10.G9@7616.4,7690.1 ; v1(7600.6,7779.6) v1@7603.5,7779.6 ; v1(7632.1,7779.6) 7629.3,7779.6 U10.L9@7616.4,7792.5 v1@7603.5,7779.6 ; U10.C6@7710.9,7587.7 v1@7723.8,7574.9 ; U10.F6@7710.9,7664.5 v1@7723.8,7677.4 ; U10.G6@7710.9,7690.1 7723.6,7677.4 v1@7723.8,7677.4 ; U10.L6@7710.9,7792.5 7723.8,7805.4 v1(7726.6,7805.4) 7739.3,7818.1 U10.M5@7742.3,7818.1 ; U10.M6@7710.9,7818.1 7713.9,7818.1 v1(7726.6,7830.8) ; U10.N6@7710.9,7843.6 7723.8,7856.5 v1(7726.6,7856.5) 7729.5,7856.5 U10.N5@7742.4,7843.6 ; U10.R6@7710.9,7894.8 7723.6,7907.5 v1@7723.8,7907.5 ; v1(7726.6,7677.4) v1@7723.8,7677.4 ; C131.1@7730.8,8043.6 v1(7730.8,8072.8) ; v1(7758.1,7549.3) 7755.2,7549.3 U10.B5@7742.3,7562.2 ; U10.J4@7773.8,7741.3 7778.2,7741.3 v1(7788.2,7751.2) ; U10.M4@7773.8,7818.1 7770.8,7818.1 v1(7758.1,7830.8) ; v1(7789.6,7574.9) 7792.4,7574.9 U10.C3@7805.3,7587.7 ; U10.P3@7805.3,7869.2 7802.3,7869.2 v1(7789.6,7856.5) 7786.7,7856.5 U10.N4@7773.8,7843.6 ; v1(7819.3,7624.7) 7816.7,7624.7 U10.D3@7805.3,7613.3 7792.4,7626.2 v1(7789.6,7626.2) 7786.5,7626.2 U10.E4@7773.8,7638.9 ; v1(7821.1,7600.6) 7818.2,7600.6 U10.C3@7805.3,7587.7 ; v1(7821.1,7677.2) 7818.2,7677.2 U10.G3@7805.3,7690.1 7792.4,7677.2 v1(7789.6,7677.2) v1@7786.7,7677.2 ; U10.B2@7836.8,7562.2 7823.9,7575 v1(7821.1,7575) 7808.4,7587.7 U10.C3@7805.3,7587.7 ; U10.H2@7836.8,7715.7 7843.8,7715.7 v1(7852.9,7706.6) ; U10.K2@7836.8,7766.9 7851,7781.1 v1(7853.1,7781.1) ; U10.T2@7836.8,7920.4 7849.7,7933.3 v1(7852.6,7933.3) ; v1(7930.2,8088.3) C133.2@7953.5,8088.3 7969.6,8088.3 v1(7978.7,8079.3) ; v1(7998.3,7601.7) C129.2@7998.3,7624.5 ; v1@7723.8,7574.9 7723.6,7574.9 U10.B6@7710.9,7562.2 7723.8,7549.3 v1(7726.6,7549.3) 7739.5,7562.2 U10.B5@7742.3,7562.2 ; v1@7723.8,7574.9 v1(7726.6,7574.9) 7739.5,7587.7 U10.C5@7742.3,7587.7 7755.2,7574.9 v1(7758.1,7574.9) 7745.4,7562.2 U10.B5@7742.3,7562.2 ; v1@7723.8,7907.5 U10.T6@7710.9,7920.4 7723.8,7933.3 v1(7726.6,7933.3) 7729.5,7933.3 U10.T5@7742.3,7920.4 v1@7729.5,7907.5 ; v1@7723.8,7907.5 v1(7726.6,7907.5) v1@7729.5,7907.5 ; v1@7729.4,7651.6 v1(7726.6,7651.6) 7723.6,7651.6 U10.E6@7710.9,7638.9 7713.7,7638.9 v1(7726.6,7626) 7729.4,7626 U10.E5@7742.3,7638.9 ; v1@7729.4,7651.6 7729.7,7651.6 U10.E5@7742.3,7638.9 ; v1@7729.4,7651.6 U10.F5@7742.3,7664.5 ; v1@7729.5,7907.5 7729.7,7907.5 U10.R5@7742.3,7894.8 7755,7907.5 v1@7755.3,7907.5 ; U10.E5@7742.3,7638.9 7755,7651.6 v1(7758.1,7651.6) ; U10.E5@7742.3,7638.9 7755.2,7626 v1(7758.1,7626) 7760.9,7626 U10.E4@7773.8,7638.9 ; U10.F5@7742.3,7664.5 7745.2,7664.5 v1(7758.1,7651.6) ; U10.F5@7742.3,7664.5 7755,7677.2 v1(7758.1,7677.2) 7760.9,7677.2 U10.G4@7773.8,7690.1 v1@7786.7,7677.2 ; U10.N5@7742.4,7843.6 7729.5,7830.8 7729.7,7830.8 7742.4,7818.1 7745.4,7818.1 v1(7758.1,7830.8) ; U10.N5@7742.4,7843.6 7755.3,7856.5 v1(7758.1,7856.5) 7761,7856.5 U10.N4@7773.8,7843.6 ; U10.N5@7742.4,7843.6 7755.3,7830.8 v1(7758.1,7830.8) ; v1@7755.3,7907.5 7742.4,7920.4 7755.3,7933.3 v1(7758.1,7933.3) 7761,7933.3 U10.T4@7773.8,7920.4 ; v1@7755.3,7907.5 v1(7758.1,7907.5) v1@7761,7907.5 ; v1(7758.1,7651.6) v1@7760.9,7651.6 ; v1(7758.1,7830.8) 7761,7830.8 U10.N4@7773.8,7843.6 ; v1@7760.9,7651.6 7761.2,7651.6 U10.E4@7773.8,7638.9 ; v1@7760.9,7651.6 U10.F4@7773.8,7664.5 7786.5,7677.2 v1@7786.7,7677.2 ; v1@7761,7907.5 7761.2,7907.5 U10.R4@7773.8,7894.8 7776.9,7894.8 v1(7789.6,7907.5) ; v1@7761,7907.5 U10.T4@7773.8,7920.4 ; U10.T4@7773.8,7920.4 7786.7,7933.3 v1(7789.6,7933.3) 7792.4,7933.3 U10.T3@7805.3,7920.4 7792.4,7907.5 v1(7789.6,7907.5) ; U10.T4@7773.8,7920.4 7786.7,7907.5 v1(7789.6,7907.5)
  Top Layer w16: v1(7315.4,7744.5) 7327.4,7744.5 R86.1@7338.6,7733.3 C121.1@7338.6,7773.3 v1(7317,7773.3) ; v1(7658.4,7394.5) 7682.1,7394.5 C130.1@7682.3,7394.2 v1(7682.3,7365.3) ; v1(7706.9,7394) 7729.4,7394 C134.1@7729.6,7394.2 v1(7729.6,7365.7) ; v1(7796,7365.3) R82.2@7796,7394.2 R81.2@7835.4,7394.2 ; v1(7835.4,7365.3) R81.2@7835.4,7394.2 ; v1(7874.9,7365.3) C135.1@7874.9,7394.2 ; v1(7916.9,7365.3) C136.1@7916.9,7394.2 ; v1(7955.9,7365.3) R85.1@7955.9,7394.2 ; v1(7982.1,7394.2) R85.1@7955.9,7394.2 ; R81.2@7835.4,7394.2 C135.1@7874.9,7394.2 ; C135.1@7874.9,7394.2 C136.1@7916.9,7394.2 ; C136.1@7916.9,7394.2 R85.1@7955.9,7394.2
  Bottom Layer w4: v1(6992.8,7796.6) 7012.8,7776.6 7032.1,7776.6 7049.5,7759.2
  Bottom Layer w8: v1(6914,8072.2) 6914,8248.1 7047.5,8381.6 ; v1(6953.4,8072.2) 6941.7,8083.9 6941.7,8235.6 7069.1,8363
  Bottom Layer w10: v1(6933.7,7875.3) 6934.4,7874.6 C137.2@6934.4,7852.4 ; v1(6933.7,7895) 6961.5,7895 C138.1@6962.1,7895.6 ; C122.2@7587.2,7757.8 7587.2,7766.1 v1(7600.6,7779.6) ; v1(7663.6,7702.8) 7663.6,7706.8 7684.7,7727.9 ; 7702.8,7810 7705.9,7810 v1(7726.6,7830.8)
  other v1: 7120.3,7350.3 6837.7,7421.4 6973.9,7483 7151.6,7679.7 6682.6,7683.3 6855.2,7895.2 7472.1,7988 7051.8,7992.9 7213.3,8006.5 7176.4,8029.1
GPIO0-LDO: R70.2
GPIO1-LDO: R69.2 R74.1
HBIAS: C173.2 R113.2 U34.B16 | length 128.9
  Top Layer w3.5: 6665,7980.6 6685.2,7980.6 6688.2,7983.6 6707.3,7983.6 U34.B16@6717.2,7993.4
  Top Layer w4: 6593.6,7980.6 6665,7980.6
